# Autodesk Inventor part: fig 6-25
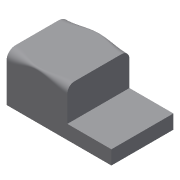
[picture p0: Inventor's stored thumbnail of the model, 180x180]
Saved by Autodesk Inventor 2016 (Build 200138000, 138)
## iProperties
Created: 2004-05
Part Number: fig 6-25
Document SubType Name: Modeling
Designer: CADCIM Technologies
Manufacturer: Standard
Standards Organization: Custom
Density: 1 g/cm^3
Material: Generic
Appearance: Default
Author: CADCIM Technologies
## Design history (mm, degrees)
node "Sketch1"
sketch "Sketch2"
  geometry: L1 (0.098, 47.711)-(0.098, 0.049); L2 (0.098, 0.049)-(-105.483, 0.049); L3 (-105.483, 0.049)-(-105.483, 14.192); L4 (-105.483, 14.192)-(-61.139, 14.192); L5 (-61.139, 14.192)-(-61.139, 47.711); L6 (-61.139, 47.711)-(0.098, 47.711)
  constraints: 12 end point, 3 parallel, 2 perpendicular, 1 vertical
extrude "Extrusion1" new body sketch "Sketch2" stored distance "d0" = 62.5; taper "d1" = 0 deg
fillet "Fillet9" dims "d61" = 10, "d62" = 8, "d63" = 2, "d64" = 5
fillet "Fillet10" dims "d65" = 8, "d66" = 10, "d67" = 2, "d68" = 5
body "Solid1"
